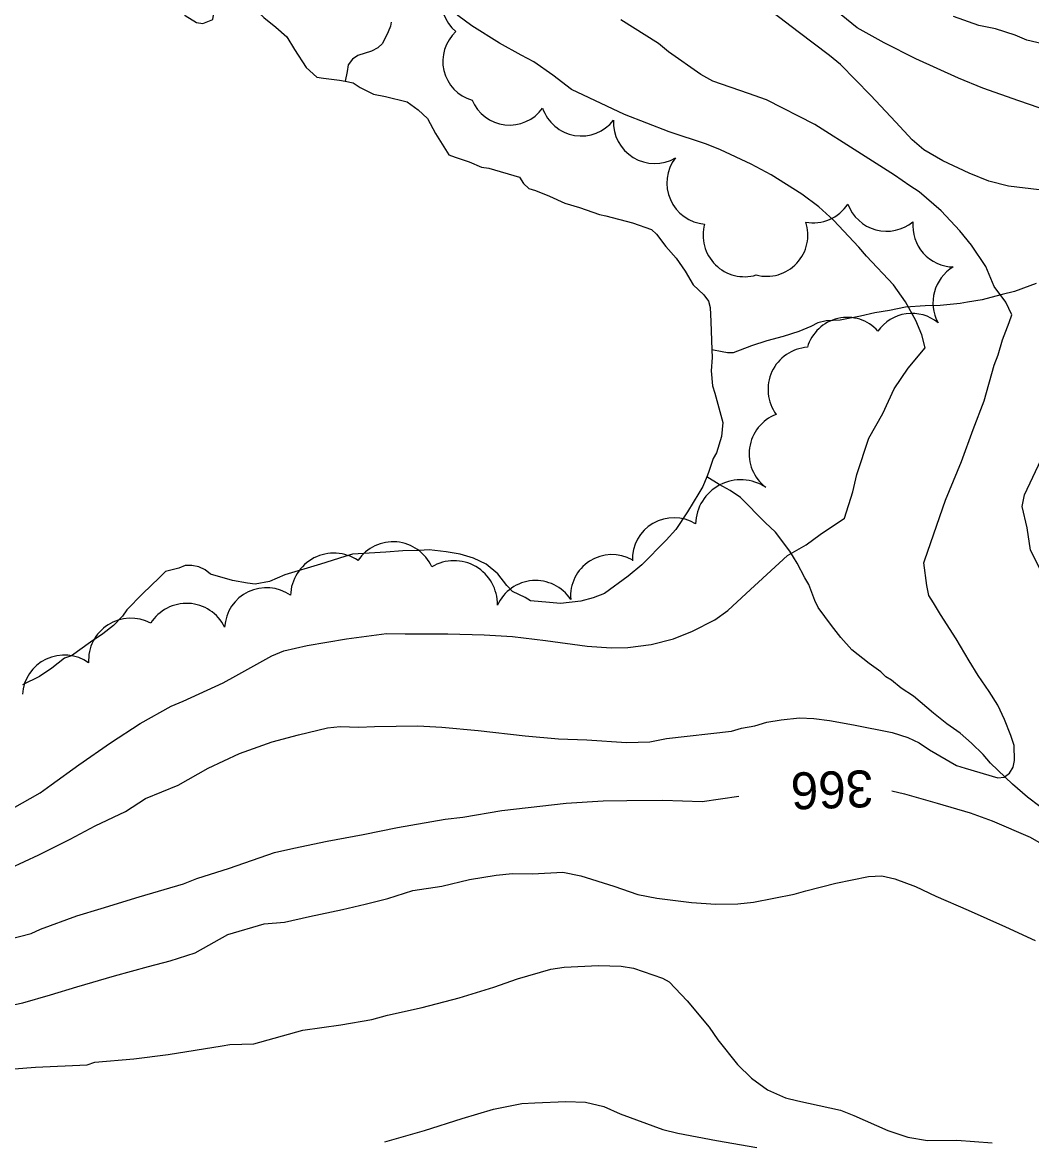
# Model space of a CAD drawing. Extents: x 287698 to 290158, y 5234163 to 5237182.
# Drawn here: x 288887.2 to 288969.2, y 5235213.3 to 5235304.2 of the extents above; entities that cross this region are included whole.
import ezdxf

# ---------------------------------------------------------------- set-up
doc = ezdxf.new("R2010")
doc.units = 0
for name, color, linetype in [('Niveau 1', 7, 'Continuous'), ('Niveau 2', 7, 'Continuous'), ('Niveau 4', 7, 'Continuous'), ('Niveau 44', 7, 'Continuous')]:
    doc.layers.add(name, color=color, linetype=linetype)

msp = doc.modelspace()

# ---------------------------------------------------------------- linework, layer by layer
at = {"layer": 'Niveau 1'}
for points in [[(288971.19, 5235302.16), (288968.77, 5235302.73), (288967.81, 5235303.14), (288966.23, 5235303.64), (288964.88, 5235303.92), (288962.8, 5235304.65)], [(288922.67, 5235224.97), (288925.48, 5235225.82), (288927.4, 5235226.5), (288930.12, 5235227.29), (288931.19, 5235227.45), (288933.99, 5235227.59), (288935.82, 5235227.54), (288936.83, 5235227.36), (288939.19, 5235226.57), (288939.73, 5235226.27), (288941.18, 5235224.71), (288942.96, 5235222.57), (288943.68, 5235221.56), (288945.27, 5235219.54), (288946.41, 5235218.45), (288947.71, 5235217.49), (288949.18, 5235216.85), (288950.16, 5235216.61), (288953.63, 5235215.85), (288954.72, 5235215.4), (288957.49, 5235214.2), (288959.11, 5235213.66), (288960.71, 5235213.39), (288963.07, 5235213.41), (288965.96, 5235213.18)], [(288886.53, 5235219.2), (288888.27, 5235219.34), (288892.48, 5235219.52), (288893.09, 5235219.74), (288896.27, 5235220), (288899.04, 5235220.36), (288903.44, 5235221.07), (288904.05, 5235221.18), (288906, 5235221.22), (288909.99, 5235222.33), (288913.06, 5235222.77), (288915.59, 5235223.21), (288916.86, 5235223.55), (288919.68, 5235224.17), (288922.67, 5235224.97)]]:
    msp.add_lwpolyline(points, dxfattribs=at)
at = {"layer": 'Niveau 2'}
for points in [[(288977.08, 5235295.01), (288977.02, 5235295.01), (288975.25, 5235295.33), (288968.11, 5235297.81), (288965.19, 5235298.84), (288963.23, 5235299.65), (288959.75, 5235301.21), (288957.18, 5235302.5), (288954.98, 5235303.72), (288953.27, 5235305.13), (288952.34, 5235306.07), (288950.38, 5235308.52)], [(288942.75, 5235294.28), (288939.72, 5235295.28), (288936.11, 5235296.69), (288931.8, 5235298.73), (288930.28, 5235299.89), (288928.75, 5235300.97), (288927.71, 5235301.5), (288925.94, 5235302.49), (288923.69, 5235303.88), (288922.56, 5235304.73), (288921.83, 5235305.43), (288921.53, 5235305.62)], [(288969.78, 5235290.58), (288967.29, 5235290.88), (288965.68, 5235291.29), (288964.08, 5235291.92), (288961.94, 5235292.92), (288960.41, 5235293.82), (288959.46, 5235294.64), (288958.13, 5235296.07), (288956.06, 5235298.27), (288953.64, 5235300.75), (288952.73, 5235301.47), (288950.21, 5235303.4), (288948.13, 5235304.97)], [(288959.26, 5235290.91), (288958.01, 5235291.77), (288955.05, 5235293.65), (288951.54, 5235295.87), (288947.63, 5235297.89), (288946.17, 5235298.39), (288943.27, 5235299.41), (288942.29, 5235299.94), (288939.68, 5235301.77), (288938.86, 5235302.45), (288935.81, 5235304.39)], [(288891.8, 5235243.89), (288894.37, 5235245.68), (288896.77, 5235247.24), (288899.29, 5235248.65), (288900.27, 5235249.05), (288903.5, 5235250.54), (288904.54, 5235251.11), (288907.47, 5235252.74), (288908.43, 5235253.13), (288910.33, 5235253.56), (288913.52, 5235254.11), (288916.78, 5235254.54), (288918.29, 5235254.51), (288921.75, 5235254.51), (288924.7, 5235254.44), (288927, 5235254.29), (288929.68, 5235253.98), (288933.08, 5235253.52), (288935.02, 5235253.37), (288936.36, 5235253.4), (288938.26, 5235253.66), (288940.08, 5235254.12), (288941.63, 5235254.73), (288943.43, 5235255.66), (288944.49, 5235256.42), (288945.98, 5235257.79), (288949.32, 5235260.89), (288950.84, 5235261.74), (288951.99, 5235262.58), (288953.97, 5235263.91), (288954.63, 5235266.04), (288954.95, 5235267.45), (288955.95, 5235270.4), (288957.08, 5235272.42), (288957.99, 5235274.42), (288959.12, 5235276.09), (288960.5, 5235277.75), (288960.25, 5235278.81), (288959.76, 5235279.97), (288958.91, 5235281.47), (288957.94, 5235282.86), (288955.75, 5235285.18), (288955.12, 5235285.93), (288953.07, 5235288.11), (288951.89, 5235289.19), (288950.49, 5235290.23), (288948, 5235291.79), (288946.37, 5235292.66), (288943.9, 5235293.81), (288942.75, 5235294.28)], [(288960.48, 5235260.53), (288962.15, 5235265.38), (288963.45, 5235268.51), (288964.42, 5235271.1), (288965.29, 5235273.45), (288966.11, 5235276.34), (288966.45, 5235277.17), (288966.78, 5235278.4), (288967.33, 5235279.81), (288967.56, 5235280.41), (288967.07, 5235281.46), (288966.11, 5235282.72), (288965.43, 5235284.36), (288964.28, 5235286.09), (288963.32, 5235287.24), (288961.82, 5235288.86), (288960.03, 5235290.41), (288959.26, 5235290.91)], [(288971.07, 5235257.33), (288969.05, 5235261.31), (288968.78, 5235263.12), (288968.39, 5235264.87), (288968.57, 5235265.8), (288969.94, 5235268.68)], [(288939.5, 5235246.02), (288944.78, 5235246.62), (288945.6, 5235246.86), (288946.68, 5235247.04), (288947.65, 5235247.35), (288948.83, 5235247.55), (288950.31, 5235247.7), (288951.48, 5235247.65), (288952.73, 5235247.47), (288954.68, 5235247.13), (288957.82, 5235246.5), (288959.11, 5235246.11), (288960.03, 5235245.66), (288960.85, 5235245.11), (288963.06, 5235243.83), (288963.75, 5235243.6), (288966.41, 5235242.83), (288966.93, 5235242.88), (288967.37, 5235243.21), (288967.66, 5235243.68), (288967.76, 5235244.24), (288967.73, 5235245.46), (288967.46, 5235246.26), (288966.94, 5235247.57), (288966.4, 5235248.72), (288965.72, 5235249.83), (288964.81, 5235251.13), (288964.07, 5235252.32), (288963.04, 5235254.12), (288961.76, 5235256.08), (288961.2, 5235257.03), (288960.82, 5235257.62), (288960.64, 5235258.45), (288960.41, 5235260.29), (288960.48, 5235260.53)], [(288895.58, 5235240.09), (288897.2, 5235241.15), (288899.85, 5235242.24), (288902.29, 5235243.61), (288904.83, 5235244.79), (288907.48, 5235245.76), (288909.63, 5235246.32), (288911.98, 5235246.88), (288913.01, 5235247), (288914.54, 5235246.95), (288915.79, 5235247), (288919.31, 5235247.05), (288921.28, 5235246.95), (288924.23, 5235246.66), (288928.04, 5235246.24), (288930.74, 5235245.99), (288933.05, 5235245.9), (288936.26, 5235245.69), (288938.16, 5235245.74), (288939.5, 5235246.02)], [(288886.41, 5235240.34), (288888.66, 5235241.6), (288889.56, 5235242.27), (288891.8, 5235243.89)], [(288896.69, 5235233.16), (288900.29, 5235234.23), (288901.37, 5235234.65), (288904.02, 5235235.5), (288907.68, 5235236.76), (288909.26, 5235237.12), (288911.95, 5235237.69), (288914.89, 5235238.22), (288917.68, 5235238.79), (288921.55, 5235239.47), (288922.97, 5235239.64), (288926.15, 5235240.17), (288928.27, 5235240.42), (288931.36, 5235240.76), (288934.36, 5235240.97), (288936.28, 5235240.99), (288939.2, 5235241.02), (288942.4, 5235240.91), (288943.9, 5235241.12), (288945.37, 5235241.35)], [(288957.81, 5235241.78), (288958.82, 5235241.53), (288961.48, 5235240.76), (288964.16, 5235239.99), (288965.95, 5235239.34), (288969.04, 5235238.02), (288973.19, 5235235.62)], [(288886.21, 5235235.5), (288888.55, 5235236.58), (288891.1, 5235237.86), (288893.13, 5235238.93), (288895.58, 5235240.09)], [(288903.88, 5235230.1), (288906.85, 5235230.98), (288908.48, 5235231.11), (288910.53, 5235231.56), (288913.19, 5235232.13), (288915.03, 5235232.58), (288916.87, 5235233.02), (288918.91, 5235233.67), (288921.27, 5235234.03), (288923.51, 5235234.58), (288925.67, 5235234.93), (288927, 5235235.06), (288928.63, 5235235.02), (288931.1, 5235235.17), (288932.54, 5235234.88), (288935.23, 5235234.04), (288937.18, 5235233.36), (288938.73, 5235233.05), (288941.54, 5235232.71), (288943.51, 5235232.57), (288945.3, 5235232.59), (288946.58, 5235232.74), (288949.87, 5235233.39), (288950.82, 5235233.66), (288953.27, 5235234.28), (288955.91, 5235234.81), (288957, 5235234.86), (288958.05, 5235234.63), (288959.72, 5235234.01), (288961.39, 5235233.21), (288963.99, 5235232.07), (288967.04, 5235230.73), (288969.43, 5235229.62)], [(288884.83, 5235229.4), (288887.93, 5235230.2), (288888.67, 5235230.53), (288891.62, 5235231.62), (288893.61, 5235232.23), (288896.69, 5235233.16)], [(288885, 5235224.1), (288887.24, 5235224.55), (288889.49, 5235225.21), (288891.64, 5235225.86), (288894.7, 5235226.74), (288897.46, 5235227.52), (288899.2, 5235227.96), (288901.24, 5235228.62), (288903.88, 5235230.1)], [(288916.63, 5235213.28), (288919.87, 5235214.2), (288922.91, 5235215.16), (288925.45, 5235215.93), (288927.76, 5235216.37), (288928.81, 5235216.44)], [(288928.81, 5235216.44), (288931.34, 5235216.55), (288932.93, 5235216.49), (288934.43, 5235216.13), (288935.76, 5235215.55), (288939.2, 5235214.27), (288940.42, 5235213.97), (288943.56, 5235213.39), (288946.85, 5235212.81)]]:
    msp.add_lwpolyline(points, dxfattribs=at)
at = {"layer": 'Niveau 4'}
for points in [[(288896.75, 5235306.35), (288897.81, 5235306.47), (288898.85, 5235306.36), (288899.26, 5235305.95), (288900.43, 5235304.74), (288901.34, 5235304.16), (288901.86, 5235304.07), (288902.67, 5235304.41), (288902.76, 5235304.92), (288903.37, 5235305.51), (288903.92, 5235305.41), (288906.42, 5235304.95), (288906.82, 5235304.57), (288907.8, 5235303.79), (288908.69, 5235303), (288909.3, 5235301.96), (288910.25, 5235300.52), (288911.12, 5235299.73), (288911.67, 5235299.63), (288912.95, 5235299.49), (288913.42, 5235299.39)], [(288917.15, 5235304.2), (288917.09, 5235303.87), (288916.92, 5235303.39), (288916.45, 5235302.45), (288916.07, 5235302.1), (288915.55, 5235301.82), (288914.45, 5235301.49), (288914, 5235301.18), (288913.67, 5235300.73), (288913.57, 5235300.18), (288913.42, 5235299.39)], [(288913.42, 5235299.39), (288914.07, 5235299.25), (288914.63, 5235298.87), (288915.71, 5235298.35), (288916.7, 5235298.16), (288918.44, 5235297.71), (288919.35, 5235297.08), (288920.11, 5235296.36), (288920.75, 5235295.15), (288921.83, 5235293.42), (288922.34, 5235293.22), (288923.49, 5235292.84), (288924.5, 5235292.42), (288925.07, 5235292.34), (288927.58, 5235291.59), (288927.9, 5235291.09), (288928.33, 5235290.69), (288928.88, 5235290.53), (288930.01, 5235290.06), (288931.25, 5235289.48), (288932.45, 5235289.13), (288934.07, 5235288.56), (288934.58, 5235288.47), (288936.74, 5235287.88), (288938.29, 5235287.35), (288938.71, 5235286.97), (288939.45, 5235285.98), (288940.29, 5235285.02), (288941.02, 5235283.98), (288941.68, 5235282.87), (288942.53, 5235282.05), (288942.91, 5235281.54), (288943.06, 5235281.02), (288943.12, 5235279.89), (288943.2, 5235277.57)], [(288969.52, 5235282.96), (288969.02, 5235282.77), (288967.77, 5235282.32), (288966.77, 5235282.07), (288966.26, 5235281.93), (288965.15, 5235281.64), (288963.94, 5235281.45), (288963.35, 5235281.35), (288961.74, 5235281.17), (288960.52, 5235281.16), (288958.91, 5235281.04), (288957.62, 5235280.78), (288956.43, 5235280.58), (288955.25, 5235280.32), (288953.61, 5235279.98), (288952.48, 5235279.94), (288951.8, 5235279.77), (288951.24, 5235279.48), (288950.26, 5235279.07), (288948.99, 5235278.66), (288947.66, 5235278.31), (288946.41, 5235277.9), (288944.91, 5235277.33), (288944.47, 5235277.35), (288944.04, 5235277.42), (288943.2, 5235277.57), (288943.2, 5235277.57)], [(288943.2, 5235277.57), (288943.22, 5235276.95), (288943.13, 5235275.87), (288943.24, 5235274.67), (288943.44, 5235274.07), (288944.09, 5235271.68), (288943.97, 5235270.54), (288943.58, 5235269.21), (288943.29, 5235268.75), (288942.91, 5235267.62), (288942.77, 5235267.26)], [(288942.77, 5235267.26), (288942.47, 5235266.48), (288942.13, 5235265.95), (288941.21, 5235264.43), (288940.27, 5235262.99), (288939.49, 5235262.13), (288937.51, 5235260.13), (288936.39, 5235259.19), (288934.48, 5235257.8), (288933.56, 5235257.43), (288932.54, 5235257.17), (288930.9, 5235256.97), (288930.02, 5235257.06)], [(288969.81, 5235240.51), (288968.81, 5235241.27), (288967.59, 5235242.32), (288965.82, 5235244.01), (288965.23, 5235244.71), (288964.28, 5235245.65), (288963.35, 5235246.46), (288962.26, 5235247.22), (288961.2, 5235248.08), (288959.55, 5235249.45), (288958.57, 5235250.11), (288957.77, 5235250.77), (288957.31, 5235251.02), (288956.91, 5235251.43), (288955.96, 5235252.11), (288954.57, 5235253.21), (288953.67, 5235254.22), (288952.9, 5235255.19), (288951.82, 5235256.66), (288951.56, 5235257.23), (288951.06, 5235258.52), (288950.73, 5235259.08), (288950.12, 5235260.27), (288949.52, 5235261.23), (288948.35, 5235262.77), (288947.52, 5235263.57), (288945.52, 5235265.59), (288944.69, 5235266.16), (288943.78, 5235266.65), (288942.77, 5235267.26)], [(288930.02, 5235257.06), (288928.46, 5235257.19), (288928.04, 5235257.47), (288927.01, 5235257.96), (288926.55, 5235258.45), (288925.82, 5235259.39), (288924.86, 5235260.18), (288923.83, 5235260.67), (288922.75, 5235260.98), (288921.61, 5235261.18), (288920.24, 5235261.35), (288919.43, 5235261.28), (288918.11, 5235261.25), (288916.73, 5235261.15), (288914.02, 5235260.98), (288913.4, 5235260.8), (288911.42, 5235260.18), (288908.52, 5235259.31), (288907.27, 5235258.78), (288906.1, 5235258.56), (288905.48, 5235258.63), (288904.28, 5235258.84), (288902.48, 5235259.36), (288902.04, 5235259.72), (288901.55, 5235259.95), (288900.98, 5235260.07), (288900.43, 5235260.06), (288899.91, 5235259.85), (288898.82, 5235259.58), (288898.35, 5235259.09), (288896.96, 5235257.77), (288895.68, 5235256.48), (288895.34, 5235255.95), (288894.6, 5235255.2), (288893.73, 5235254.52), (288892.74, 5235253.85), (288891.2, 5235252.74), (288890.62, 5235252.55), (288889.6, 5235251.72), (288888.59, 5235251.05), (288887.21, 5235250.39)]]:
    msp.add_lwpolyline(points, dxfattribs=at)
at = {"layer": 'Niveau 44'}
for centre, radius, start, end in [((288962.873, 5235287.674), 3.367, 174.77896, 268.65212), ((288964.506, 5235281.409), 3.367, 120.56923, 208.92446), ((288954.179, 5235276.852), 3.363, 41.95683, 163.7986), ((288959.435, 5235277.172), 3.363, 50.84447, 145.02339), ((288951.189, 5235274.358), 3.44, 93.98045, 216.12371), ((288949.63, 5235269.142), 3.413, 110.93795, 232.88329), ((288945.548, 5235263.346), 3.68, 56.66856, 178.37521), ((288940.106, 5235260.58), 3.368, 58.42723, 182.04397), ((288917.31, 5235258.552), 3.441, 24.15216, 145.92487), ((288912.505, 5235257.545), 3.527, 56.33221, 178.29357), ((288922.257, 5235256.935), 3.524, 358.78501, 120.84927), ((288935.085, 5235257.593), 3.366, 60.83894, 184.65949), ((288928.883, 5235255.436), 3.414, 33.49035, 155.35124), ((288907.026, 5235254.865), 3.402, 54.9531, 176.53763), ((288900.544, 5235253.558), 3.437, 26.10465, 147.98005), ((288896.005, 5235252.369), 3.422, 61.65428, 183.49384), ((288890.607, 5235249.394), 3.404, 54.36043, 176.35939)]:
    msp.add_arc(centre, radius, start, end, dxfattribs=at)
for centre, major_axis, ratio, start_param, end_param in [((288924.576, 5235305.995), (-3.244, 0.899), 0.999358, 5.301679, 7.425141), ((288924.624, 5235301.007), (-3.219, -0.64), 0.996908, 5.256894, 7.379221), ((288926.76, 5235299.122), (-0.369, -3.272), 0.999614, 5.217921, 7.346719), ((288932.562, 5235298.257), (2.319, -2.395), 0.98521, 4.272566, 6.429206), ((288938.518, 5235296.03), (2.529, -2.177), 0.989746, 3.800048, 5.959432), ((288942.861, 5235291.121), (0.757, -3.256), 0.993992, 3.825001, 5.974874), ((288951.436, 5235291.232), (2.095, 2.59), 0.999855, 3.63255, 4.817046), ((288957.366, 5235290.515), (3.098, -1.231), 0.989822, 3.860755, 5.790804), ((288945.806, 5235286.853), (2.384, -2.35), 0.990534, 3.639338, 5.785439), ((288947.639, 5235286.895), (2.285, 2.444), 0.998959, 3.637134, 5.787644)]:
    msp.add_ellipse(centre, major_axis=major_axis, ratio=ratio, start_param=start_param, end_param=end_param, dxfattribs=at)

# ---------------------------------------------------------------- texts
at = {"layer": 'Niveau 2'}
msp.add_text('366', height=2.9999, rotation=181.84837, dxfattribs=at).set_placement((288956.25, 5235243.46))

doc.saveas('drawing.dxf')
